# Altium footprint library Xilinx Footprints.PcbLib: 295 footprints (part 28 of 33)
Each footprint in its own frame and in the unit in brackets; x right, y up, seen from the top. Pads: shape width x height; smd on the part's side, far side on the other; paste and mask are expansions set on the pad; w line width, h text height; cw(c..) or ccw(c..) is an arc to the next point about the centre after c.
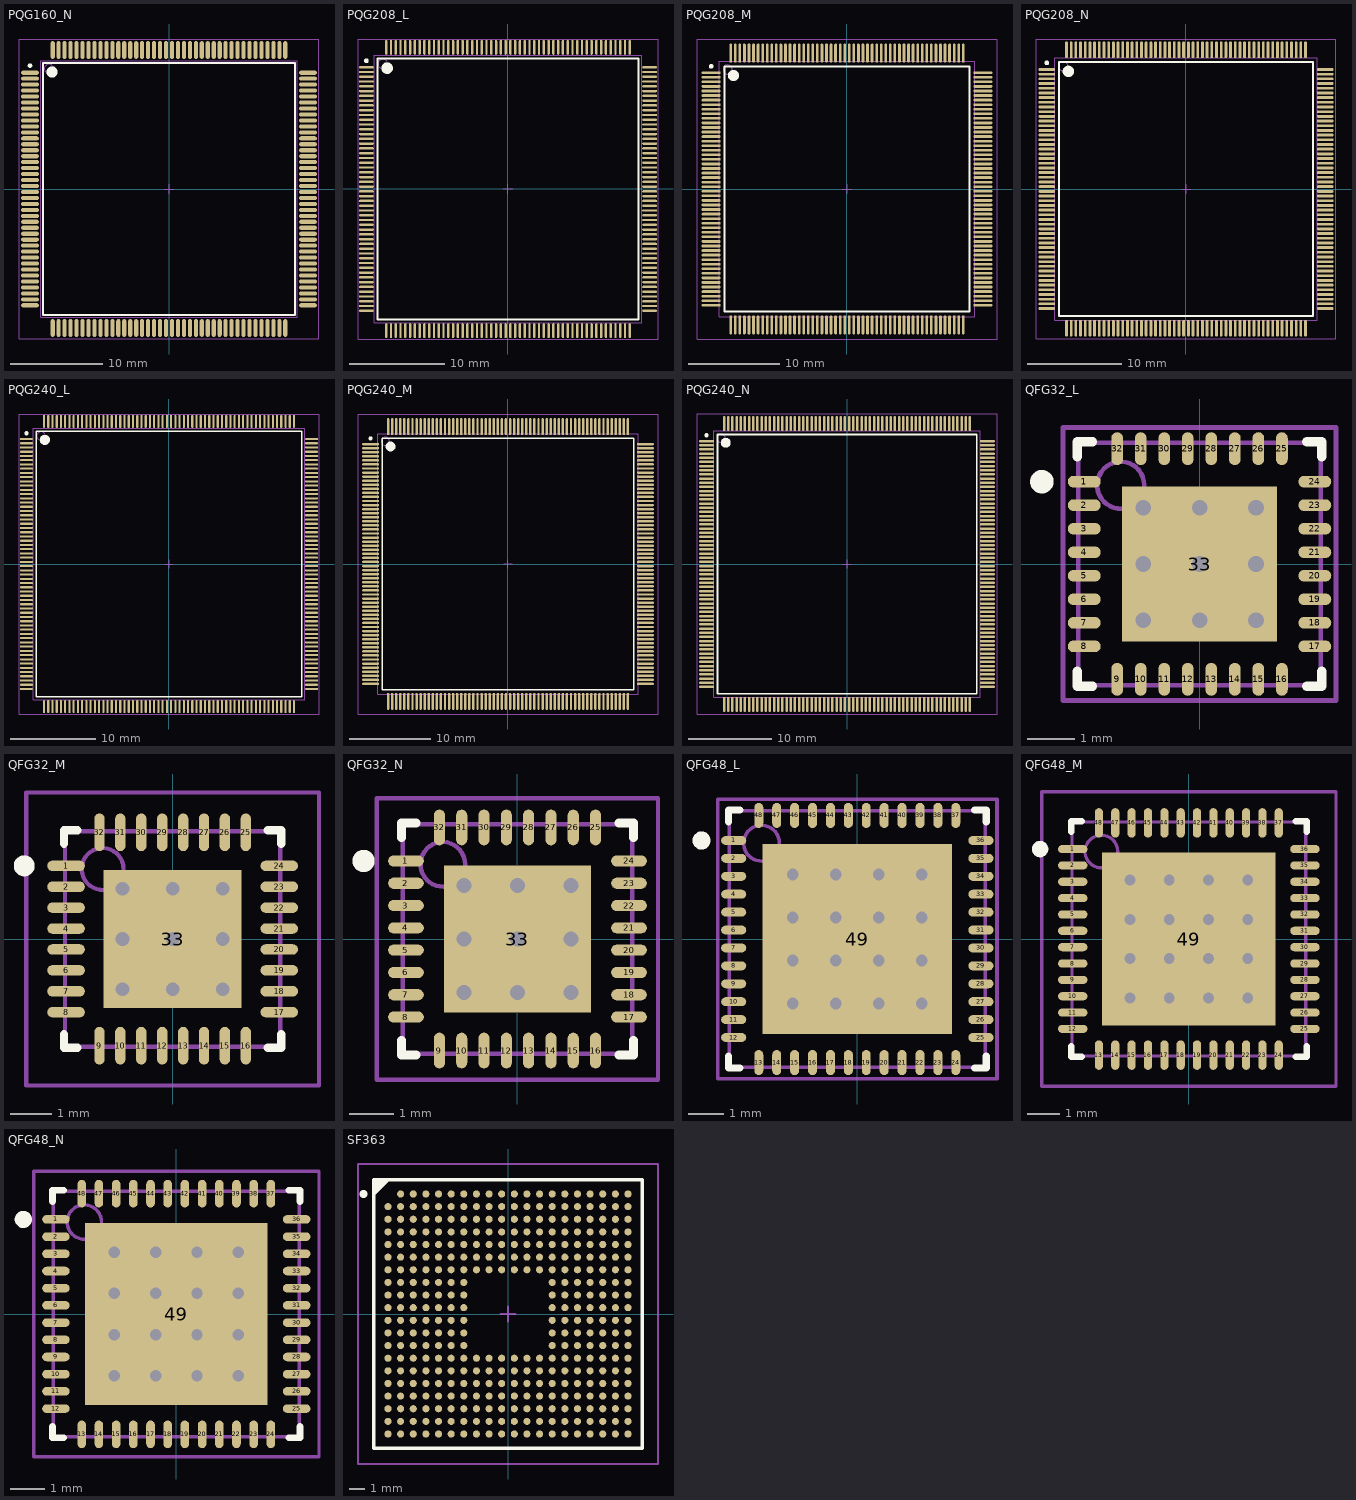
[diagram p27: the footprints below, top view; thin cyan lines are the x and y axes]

## PQG160_N [mm] "160-Pin Plastic Quad Flat Pack (PQG160) - Pb-Free, IPC Medium Density"
height 4.1
pads (160):
  oval 1.95x0.45 smd: 1(-15.15,12.675) 2(-15.15,12.025) 3(-15.15,11.375) 4(-15.15,10.725) 5(-15.15,10.075) 6(-15.15,9.425) 7(-15.15,8.775) 8(-15.15,8.125) 9(-15.15,7.475) 10(-15.15,6.825) 11(-15.15,6.175) 12(-15.15,5.525) 13(-15.15,4.875) 14(-15.15,4.225) 15(-15.15,3.575) 16(-15.15,2.925) 17(-15.15,2.275) 18(-15.15,1.625) 19(-15.15,0.975) 20(-15.15,0.325) 21(-15.15,-0.325) 22(-15.15,-0.975) 23(-15.15,-1.625) 24(-15.15,-2.275) 25(-15.15,-2.925) 26(-15.15,-3.575) 27(-15.15,-4.225) 28(-15.15,-4.875) 29(-15.15,-5.525) 30(-15.15,-6.175) 31(-15.15,-6.825) 32(-15.15,-7.475) 33(-15.15,-8.125) 34(-15.15,-8.775) 35(-15.15,-9.425) 36(-15.15,-10.075) 37(-15.15,-10.725) 38(-15.15,-11.375) 39(-15.15,-12.025) 40(-15.15,-12.675) 81(15.15,-12.675) 82(15.15,-12.025) 83(15.15,-11.375) 84(15.15,-10.725) 85(15.15,-10.075) 86(15.15,-9.425) 87(15.15,-8.775) 88(15.15,-8.125) 89(15.15,-7.475) 90(15.15,-6.825) 91(15.15,-6.175) 92(15.15,-5.525) 93(15.15,-4.875) 94(15.15,-4.225) 95(15.15,-3.575) 96(15.15,-2.925) 97(15.15,-2.275) 98(15.15,-1.625) 99(15.15,-0.975) 100(15.15,-0.325) 101(15.15,0.325) 102(15.15,0.975) 103(15.15,1.625) 104(15.15,2.275) 105(15.15,2.925) 106(15.15,3.575) 107(15.15,4.225) 108(15.15,4.875) 109(15.15,5.525) 110(15.15,6.175) 111(15.15,6.825) 112(15.15,7.475) 113(15.15,8.125) 114(15.15,8.775) 115(15.15,9.425) 116(15.15,10.075) 117(15.15,10.725) 118(15.15,11.375) 119(15.15,12.025) 120(15.15,12.675)
  oval 0.45x1.95 smd: 41(-12.675,-15.15) 42(-12.025,-15.15) 43(-11.375,-15.15) 44(-10.725,-15.15) 45(-10.075,-15.15) 46(-9.425,-15.15) 47(-8.775,-15.15) 48(-8.125,-15.15) 49(-7.475,-15.15) 50(-6.825,-15.15) 51(-6.175,-15.15) 52(-5.525,-15.15) 53(-4.875,-15.15) 54(-4.225,-15.15) 55(-3.575,-15.15) 56(-2.925,-15.15) 57(-2.275,-15.15) 58(-1.625,-15.15) 59(-0.975,-15.15) 60(-0.325,-15.15) 61(0.325,-15.15) 62(0.975,-15.15) 63(1.625,-15.15) 64(2.275,-15.15) 65(2.925,-15.15) 66(3.575,-15.15) 67(4.225,-15.15) 68(4.875,-15.15) 69(5.525,-15.15) 70(6.175,-15.15) 71(6.825,-15.15) 72(7.475,-15.15) 73(8.125,-15.15) 74(8.775,-15.15) 75(9.425,-15.15) 76(10.075,-15.15) 77(10.725,-15.15) 78(11.375,-15.15) 79(12.025,-15.15) 80(12.675,-15.15) 121(12.675,15.15) 122(12.025,15.15) 123(11.375,15.15) 124(10.725,15.15) 125(10.075,15.15) 126(9.425,15.15) 127(8.775,15.15) 128(8.125,15.15) 129(7.475,15.15) 130(6.825,15.15) 131(6.175,15.15) 132(5.525,15.15) 133(4.875,15.15) 134(4.225,15.15) 135(3.575,15.15) 136(2.925,15.15) 137(2.275,15.15) 138(1.625,15.15) 139(0.975,15.15) 140(0.325,15.15) 141(-0.325,15.15) 142(-0.975,15.15) 143(-1.625,15.15) 144(-2.275,15.15) 145(-2.925,15.15) 146(-3.575,15.15) 147(-4.225,15.15) 148(-4.875,15.15) 149(-5.525,15.15) 150(-6.175,15.15) 151(-6.825,15.15) 152(-7.475,15.15) 153(-8.125,15.15) 154(-8.775,15.15) 155(-9.425,15.15) 156(-10.075,15.15) 157(-10.725,15.15) 158(-11.375,15.15) 159(-12.025,15.15) 160(-12.675,15.15)
Top Overlay:
  circle w0.6: c-12.75,12.75 r0.3
  circle w0.25: c-15.15,13.45 r0.125
  lines w0.2: -13.75,-13.75 13.75,-13.75 13.75,13.75 -13.75,13.75 -13.75,-13.75
Mechanical 13:
  circle w0.1: c-13.1,13.1 r0.5
  lines w0.1: -14,-14 14,-14 14,14 -14,14 -14,-14
Mechanical 15:
  lines w0.1: -0.5,0 0.5,0 ; 0,-0.5 0,0.5 ; -16.35,-16.35 16.35,-16.35 16.35,16.35 -16.35,16.35 -16.35,-16.35
3D body: height 4.1, standoff 0, extent -14,-14 14,14

## PQG208_L [mm] "208-Pin Plastic Quad Flat Pack (PQG208) - Pb-Free, IPC High Density"
height 4.1
pads (208):
  oval 1.55x0.25 smd: 1(-14.825,12.75) 2(-14.825,12.25) 3(-14.825,11.75) 4(-14.825,11.25) 5(-14.825,10.75) 6(-14.825,10.25) 7(-14.825,9.75) 8(-14.825,9.25) 9(-14.825,8.75) 10(-14.825,8.25) 11(-14.825,7.75) 12(-14.825,7.25) 13(-14.825,6.75) 14(-14.825,6.25) 15(-14.825,5.75) 16(-14.825,5.25) 17(-14.825,4.75) 18(-14.825,4.25) 19(-14.825,3.75) 20(-14.825,3.25) 21(-14.825,2.75) 22(-14.825,2.25) 23(-14.825,1.75) 24(-14.825,1.25) 25(-14.825,0.75) 26(-14.825,0.25) 27(-14.825,-0.25) 28(-14.825,-0.75) 29(-14.825,-1.25) 30(-14.825,-1.75) 31(-14.825,-2.25) 32(-14.825,-2.75) 33(-14.825,-3.25) 34(-14.825,-3.75) 35(-14.825,-4.25) 36(-14.825,-4.75) 37(-14.825,-5.25) 38(-14.825,-5.75) 39(-14.825,-6.25) 40(-14.825,-6.75) 41(-14.825,-7.25) 42(-14.825,-7.75) 43(-14.825,-8.25) 44(-14.825,-8.75) 45(-14.825,-9.25) 46(-14.825,-9.75) 47(-14.825,-10.25) 48(-14.825,-10.75) 49(-14.825,-11.25) 50(-14.825,-11.75) 51(-14.825,-12.25) 52(-14.825,-12.75) 105(14.825,-12.75) 106(14.825,-12.25) 107(14.825,-11.75) 108(14.825,-11.25) 109(14.825,-10.75) 110(14.825,-10.25) 111(14.825,-9.75) 112(14.825,-9.25) 113(14.825,-8.75) 114(14.825,-8.25) 115(14.825,-7.75) 116(14.825,-7.25) 117(14.825,-6.75) 118(14.825,-6.25) 119(14.825,-5.75) 120(14.825,-5.25) 121(14.825,-4.75) 122(14.825,-4.25) 123(14.825,-3.75) 124(14.825,-3.25) 125(14.825,-2.75) 126(14.825,-2.25) 127(14.825,-1.75) 128(14.825,-1.25) 129(14.825,-0.75) 130(14.825,-0.25) 131(14.825,0.25) 132(14.825,0.75) 133(14.825,1.25) 134(14.825,1.75) 135(14.825,2.25) 136(14.825,2.75) 137(14.825,3.25) 138(14.825,3.75) 139(14.825,4.25) 140(14.825,4.75) 141(14.825,5.25) 142(14.825,5.75) 143(14.825,6.25) 144(14.825,6.75) 145(14.825,7.25) 146(14.825,7.75) 147(14.825,8.25) 148(14.825,8.75) 149(14.825,9.25) 150(14.825,9.75) 151(14.825,10.25) 152(14.825,10.75) 153(14.825,11.25) 154(14.825,11.75) 155(14.825,12.25) 156(14.825,12.75)
  oval 0.25x1.55 smd: 53(-12.75,-14.825) 54(-12.25,-14.825) 55(-11.75,-14.825) 56(-11.25,-14.825) 57(-10.75,-14.825) 58(-10.25,-14.825) 59(-9.75,-14.825) 60(-9.25,-14.825) 61(-8.75,-14.825) 62(-8.25,-14.825) 63(-7.75,-14.825) 64(-7.25,-14.825) 65(-6.75,-14.825) 66(-6.25,-14.825) 67(-5.75,-14.825) 68(-5.25,-14.825) 69(-4.75,-14.825) 70(-4.25,-14.825) 71(-3.75,-14.825) 72(-3.25,-14.825) 73(-2.75,-14.825) 74(-2.25,-14.825) 75(-1.75,-14.825) 76(-1.25,-14.825) 77(-0.75,-14.825) 78(-0.25,-14.825) 79(0.25,-14.825) 80(0.75,-14.825) 81(1.25,-14.825) 82(1.75,-14.825) 83(2.25,-14.825) 84(2.75,-14.825) 85(3.25,-14.825) 86(3.75,-14.825) 87(4.25,-14.825) 88(4.75,-14.825) 89(5.25,-14.825) 90(5.75,-14.825) 91(6.25,-14.825) 92(6.75,-14.825) 93(7.25,-14.825) 94(7.75,-14.825) 95(8.25,-14.825) 96(8.75,-14.825) 97(9.25,-14.825) 98(9.75,-14.825) 99(10.25,-14.825) 100(10.75,-14.825) 101(11.25,-14.825) 102(11.75,-14.825) 103(12.25,-14.825) 104(12.75,-14.825) 157(12.75,14.825) 158(12.25,14.825) 159(11.75,14.825) 160(11.25,14.825) 161(10.75,14.825) 162(10.25,14.825) 163(9.75,14.825) 164(9.25,14.825) 165(8.75,14.825) 166(8.25,14.825) 167(7.75,14.825) 168(7.25,14.825) 169(6.75,14.825) 170(6.25,14.825) 171(5.75,14.825) 172(5.25,14.825) 173(4.75,14.825) 174(4.25,14.825) 175(3.75,14.825) 176(3.25,14.825) 177(2.75,14.825) 178(2.25,14.825) 179(1.75,14.825) 180(1.25,14.825) 181(0.75,14.825) 182(0.25,14.825) 183(-0.25,14.825) 184(-0.75,14.825) 185(-1.25,14.825) 186(-1.75,14.825) 187(-2.25,14.825) 188(-2.75,14.825) 189(-3.25,14.825) 190(-3.75,14.825) 191(-4.25,14.825) 192(-4.75,14.825) 193(-5.25,14.825) 194(-5.75,14.825) 195(-6.25,14.825) 196(-6.75,14.825) 197(-7.25,14.825) 198(-7.75,14.825) 199(-8.25,14.825) 200(-8.75,14.825) 201(-9.25,14.825) 202(-9.75,14.825) 203(-10.25,14.825) 204(-10.75,14.825) 205(-11.25,14.825) 206(-11.75,14.825) 207(-12.25,14.825) 208(-12.75,14.825)
Top Overlay:
  circle w0.6: c-12.65,12.65 r0.3
  circle w0.25: c-14.825,13.425 r0.125
  lines w0.2: -13.65,-13.65 13.65,-13.65 13.65,13.65 -13.65,13.65 -13.65,-13.65
Mechanical 13:
  circle w0.1: c-13.1,13.1 r0.5
  lines w0.1: -14,-14 14,-14 14,14 -14,14 -14,-14
Mechanical 15:
  lines w0.1: -0.5,0 0.5,0 ; 0,-0.5 0,0.5 ; -15.7,-15.7 15.7,-15.7 15.7,15.7 -15.7,15.7 -15.7,-15.7
3D body: height 4.1, standoff 0, extent -14,-14 14,14

## PQG208_M [mm] "208-Pin Plastic Quad Flat Pack (PQG208) - Pb-Free, IPC Low Density"
height 4.1
pads (208):
  oval 2.1x0.3 smd: 1(-14.9,12.75) 2(-14.9,12.25) 3(-14.9,11.75) 4(-14.9,11.25) 5(-14.9,10.75) 6(-14.9,10.25) 7(-14.9,9.75) 8(-14.9,9.25) 9(-14.9,8.75) 10(-14.9,8.25) 11(-14.9,7.75) 12(-14.9,7.25) 13(-14.9,6.75) 14(-14.9,6.25) 15(-14.9,5.75) 16(-14.9,5.25) 17(-14.9,4.75) 18(-14.9,4.25) 19(-14.9,3.75) 20(-14.9,3.25) 21(-14.9,2.75) 22(-14.9,2.25) 23(-14.9,1.75) 24(-14.9,1.25) 25(-14.9,0.75) 26(-14.9,0.25) 27(-14.9,-0.25) 28(-14.9,-0.75) 29(-14.9,-1.25) 30(-14.9,-1.75) 31(-14.9,-2.25) 32(-14.9,-2.75) 33(-14.9,-3.25) 34(-14.9,-3.75) 35(-14.9,-4.25) 36(-14.9,-4.75) 37(-14.9,-5.25) 38(-14.9,-5.75) 39(-14.9,-6.25) 40(-14.9,-6.75) 41(-14.9,-7.25) 42(-14.9,-7.75) 43(-14.9,-8.25) 44(-14.9,-8.75) 45(-14.9,-9.25) 46(-14.9,-9.75) 47(-14.9,-10.25) 48(-14.9,-10.75) 49(-14.9,-11.25) 50(-14.9,-11.75) 51(-14.9,-12.25) 52(-14.9,-12.75) 105(14.9,-12.75) 106(14.9,-12.25) 107(14.9,-11.75) 108(14.9,-11.25) 109(14.9,-10.75) 110(14.9,-10.25) 111(14.9,-9.75) 112(14.9,-9.25) 113(14.9,-8.75) 114(14.9,-8.25) 115(14.9,-7.75) 116(14.9,-7.25) 117(14.9,-6.75) 118(14.9,-6.25) 119(14.9,-5.75) 120(14.9,-5.25) 121(14.9,-4.75) 122(14.9,-4.25) 123(14.9,-3.75) 124(14.9,-3.25) 125(14.9,-2.75) 126(14.9,-2.25) 127(14.9,-1.75) 128(14.9,-1.25) 129(14.9,-0.75) 130(14.9,-0.25) 131(14.9,0.25) 132(14.9,0.75) 133(14.9,1.25) 134(14.9,1.75) 135(14.9,2.25) 136(14.9,2.75) 137(14.9,3.25) 138(14.9,3.75) 139(14.9,4.25) 140(14.9,4.75) 141(14.9,5.25) 142(14.9,5.75) 143(14.9,6.25) 144(14.9,6.75) 145(14.9,7.25) 146(14.9,7.75) 147(14.9,8.25) 148(14.9,8.75) 149(14.9,9.25) 150(14.9,9.75) 151(14.9,10.25) 152(14.9,10.75) 153(14.9,11.25) 154(14.9,11.75) 155(14.9,12.25) 156(14.9,12.75)
  oval 0.3x2.1 smd: 53(-12.75,-14.9) 54(-12.25,-14.9) 55(-11.75,-14.9) 56(-11.25,-14.9) 57(-10.75,-14.9) 58(-10.25,-14.9) 59(-9.75,-14.9) 60(-9.25,-14.9) 61(-8.75,-14.9) 62(-8.25,-14.9) 63(-7.75,-14.9) 64(-7.25,-14.9) 65(-6.75,-14.9) 66(-6.25,-14.9) 67(-5.75,-14.9) 68(-5.25,-14.9) 69(-4.75,-14.9) 70(-4.25,-14.9) 71(-3.75,-14.9) 72(-3.25,-14.9) 73(-2.75,-14.9) 74(-2.25,-14.9) 75(-1.75,-14.9) 76(-1.25,-14.9) 77(-0.75,-14.9) 78(-0.25,-14.9) 79(0.25,-14.9) 80(0.75,-14.9) 81(1.25,-14.9) 82(1.75,-14.9) 83(2.25,-14.9) 84(2.75,-14.9) 85(3.25,-14.9) 86(3.75,-14.9) 87(4.25,-14.9) 88(4.75,-14.9) 89(5.25,-14.9) 90(5.75,-14.9) 91(6.25,-14.9) 92(6.75,-14.9) 93(7.25,-14.9) 94(7.75,-14.9) 95(8.25,-14.9) 96(8.75,-14.9) 97(9.25,-14.9) 98(9.75,-14.9) 99(10.25,-14.9) 100(10.75,-14.9) 101(11.25,-14.9) 102(11.75,-14.9) 103(12.25,-14.9) 104(12.75,-14.9) 157(12.75,14.9) 158(12.25,14.9) 159(11.75,14.9) 160(11.25,14.9) 161(10.75,14.9) 162(10.25,14.9) 163(9.75,14.9) 164(9.25,14.9) 165(8.75,14.9) 166(8.25,14.9) 167(7.75,14.9) 168(7.25,14.9) 169(6.75,14.9) 170(6.25,14.9) 171(5.75,14.9) 172(5.25,14.9) 173(4.75,14.9) 174(4.25,14.9) 175(3.75,14.9) 176(3.25,14.9) 177(2.75,14.9) 178(2.25,14.9) 179(1.75,14.9) 180(1.25,14.9) 181(0.75,14.9) 182(0.25,14.9) 183(-0.25,14.9) 184(-0.75,14.9) 185(-1.25,14.9) 186(-1.75,14.9) 187(-2.25,14.9) 188(-2.75,14.9) 189(-3.25,14.9) 190(-3.75,14.9) 191(-4.25,14.9) 192(-4.75,14.9) 193(-5.25,14.9) 194(-5.75,14.9) 195(-6.25,14.9) 196(-6.75,14.9) 197(-7.25,14.9) 198(-7.75,14.9) 199(-8.25,14.9) 200(-8.75,14.9) 201(-9.25,14.9) 202(-9.75,14.9) 203(-10.25,14.9) 204(-10.75,14.9) 205(-11.25,14.9) 206(-11.75,14.9) 207(-12.25,14.9) 208(-12.75,14.9)
Top Overlay:
  circle w0.6: c-12.45,12.45 r0.3
  circle w0.25: c-14.9,13.45 r0.125
  lines w0.2: -13.45,-13.45 13.45,-13.45 13.45,13.45 -13.45,13.45 -13.45,-13.45
Mechanical 13:
  circle w0.1: c-13.1,13.1 r0.5
  lines w0.1: -14,-14 14,-14 14,14 -14,14 -14,-14
Mechanical 15:
  lines w0.1: -0.5,0 0.5,0 ; 0,-0.5 0,0.5 ; -16.45,-16.45 16.45,-16.45 16.45,16.45 -16.45,16.45 -16.45,-16.45
3D body: height 4.1, standoff 0, extent -14,-14 14,14

## PQG208_N [mm] "208-Pin Plastic Quad Flat Pack (PQG208) - Pb-Free, IPC Medium Density"
height 4.1
pads (208):
  oval 1.8x0.3 smd: 1(-14.85,12.75) 2(-14.85,12.25) 3(-14.85,11.75) 4(-14.85,11.25) 5(-14.85,10.75) 6(-14.85,10.25) 7(-14.85,9.75) 8(-14.85,9.25) 9(-14.85,8.75) 10(-14.85,8.25) 11(-14.85,7.75) 12(-14.85,7.25) 13(-14.85,6.75) 14(-14.85,6.25) 15(-14.85,5.75) 16(-14.85,5.25) 17(-14.85,4.75) 18(-14.85,4.25) 19(-14.85,3.75) 20(-14.85,3.25) 21(-14.85,2.75) 22(-14.85,2.25) 23(-14.85,1.75) 24(-14.85,1.25) 25(-14.85,0.75) 26(-14.85,0.25) 27(-14.85,-0.25) 28(-14.85,-0.75) 29(-14.85,-1.25) 30(-14.85,-1.75) 31(-14.85,-2.25) 32(-14.85,-2.75) 33(-14.85,-3.25) 34(-14.85,-3.75) 35(-14.85,-4.25) 36(-14.85,-4.75) 37(-14.85,-5.25) 38(-14.85,-5.75) 39(-14.85,-6.25) 40(-14.85,-6.75) 41(-14.85,-7.25) 42(-14.85,-7.75) 43(-14.85,-8.25) 44(-14.85,-8.75) 45(-14.85,-9.25) 46(-14.85,-9.75) 47(-14.85,-10.25) 48(-14.85,-10.75) 49(-14.85,-11.25) 50(-14.85,-11.75) 51(-14.85,-12.25) 52(-14.85,-12.75) 105(14.85,-12.75) 106(14.85,-12.25) 107(14.85,-11.75) 108(14.85,-11.25) 109(14.85,-10.75) 110(14.85,-10.25) 111(14.85,-9.75) 112(14.85,-9.25) 113(14.85,-8.75) 114(14.85,-8.25) 115(14.85,-7.75) 116(14.85,-7.25) 117(14.85,-6.75) 118(14.85,-6.25) 119(14.85,-5.75) 120(14.85,-5.25) 121(14.85,-4.75) 122(14.85,-4.25) 123(14.85,-3.75) 124(14.85,-3.25) 125(14.85,-2.75) 126(14.85,-2.25) 127(14.85,-1.75) 128(14.85,-1.25) 129(14.85,-0.75) 130(14.85,-0.25) 131(14.85,0.25) 132(14.85,0.75) 133(14.85,1.25) 134(14.85,1.75) 135(14.85,2.25) 136(14.85,2.75) 137(14.85,3.25) 138(14.85,3.75) 139(14.85,4.25) 140(14.85,4.75) 141(14.85,5.25) 142(14.85,5.75) 143(14.85,6.25) 144(14.85,6.75) 145(14.85,7.25) 146(14.85,7.75) 147(14.85,8.25) 148(14.85,8.75) 149(14.85,9.25) 150(14.85,9.75) 151(14.85,10.25) 152(14.85,10.75) 153(14.85,11.25) 154(14.85,11.75) 155(14.85,12.25) 156(14.85,12.75)
  oval 0.3x1.8 smd: 53(-12.75,-14.85) 54(-12.25,-14.85) 55(-11.75,-14.85) 56(-11.25,-14.85) 57(-10.75,-14.85) 58(-10.25,-14.85) 59(-9.75,-14.85) 60(-9.25,-14.85) 61(-8.75,-14.85) 62(-8.25,-14.85) 63(-7.75,-14.85) 64(-7.25,-14.85) 65(-6.75,-14.85) 66(-6.25,-14.85) 67(-5.75,-14.85) 68(-5.25,-14.85) 69(-4.75,-14.85) 70(-4.25,-14.85) 71(-3.75,-14.85) 72(-3.25,-14.85) 73(-2.75,-14.85) 74(-2.25,-14.85) 75(-1.75,-14.85) 76(-1.25,-14.85) 77(-0.75,-14.85) 78(-0.25,-14.85) 79(0.25,-14.85) 80(0.75,-14.85) 81(1.25,-14.85) 82(1.75,-14.85) 83(2.25,-14.85) 84(2.75,-14.85) 85(3.25,-14.85) 86(3.75,-14.85) 87(4.25,-14.85) 88(4.75,-14.85) 89(5.25,-14.85) 90(5.75,-14.85) 91(6.25,-14.85) 92(6.75,-14.85) 93(7.25,-14.85) 94(7.75,-14.85) 95(8.25,-14.85) 96(8.75,-14.85) 97(9.25,-14.85) 98(9.75,-14.85) 99(10.25,-14.85) 100(10.75,-14.85) 101(11.25,-14.85) 102(11.75,-14.85) 103(12.25,-14.85) 104(12.75,-14.85) 157(12.75,14.85) 158(12.25,14.85) 159(11.75,14.85) 160(11.25,14.85) 161(10.75,14.85) 162(10.25,14.85) 163(9.75,14.85) 164(9.25,14.85) 165(8.75,14.85) 166(8.25,14.85) 167(7.75,14.85) 168(7.25,14.85) 169(6.75,14.85) 170(6.25,14.85) 171(5.75,14.85) 172(5.25,14.85) 173(4.75,14.85) 174(4.25,14.85) 175(3.75,14.85) 176(3.25,14.85) 177(2.75,14.85) 178(2.25,14.85) 179(1.75,14.85) 180(1.25,14.85) 181(0.75,14.85) 182(0.25,14.85) 183(-0.25,14.85) 184(-0.75,14.85) 185(-1.25,14.85) 186(-1.75,14.85) 187(-2.25,14.85) 188(-2.75,14.85) 189(-3.25,14.85) 190(-3.75,14.85) 191(-4.25,14.85) 192(-4.75,14.85) 193(-5.25,14.85) 194(-5.75,14.85) 195(-6.25,14.85) 196(-6.75,14.85) 197(-7.25,14.85) 198(-7.75,14.85) 199(-8.25,14.85) 200(-8.75,14.85) 201(-9.25,14.85) 202(-9.75,14.85) 203(-10.25,14.85) 204(-10.75,14.85) 205(-11.25,14.85) 206(-11.75,14.85) 207(-12.25,14.85) 208(-12.75,14.85)
Top Overlay:
  circle w0.6: c-12.55,12.55 r0.3
  circle w0.25: c-14.85,13.45 r0.125
  lines w0.2: -13.55,-13.55 13.55,-13.55 13.55,13.55 -13.55,13.55 -13.55,-13.55
Mechanical 13:
  circle w0.1: c-13.1,13.1 r0.5
  lines w0.1: -14,-14 14,-14 14,14 -14,14 -14,-14
Mechanical 15:
  lines w0.1: -0.5,0 0.5,0 ; 0,-0.5 0,0.5 ; -16,-16 16,-16 16,16 -16,16 -16,-16
3D body: height 4.1, standoff 0, extent -14,-14 14,14

## PQG240_L [mm] "240-Pin Plastic Quad Flat Pack (PQG240) - Pb-Free, IPC High Density"
height 4.1
pads (240):
  oval 1.55x0.25 smd: 1(-16.825,14.75) 2(-16.825,14.25) 3(-16.825,13.75) 4(-16.825,13.25) 5(-16.825,12.75) 6(-16.825,12.25) 7(-16.825,11.75) 8(-16.825,11.25) 9(-16.825,10.75) 10(-16.825,10.25) 11(-16.825,9.75) 12(-16.825,9.25) 13(-16.825,8.75) 14(-16.825,8.25) 15(-16.825,7.75) 16(-16.825,7.25) 17(-16.825,6.75) 18(-16.825,6.25) 19(-16.825,5.75) 20(-16.825,5.25) 21(-16.825,4.75) 22(-16.825,4.25) 23(-16.825,3.75) 24(-16.825,3.25) 25(-16.825,2.75) 26(-16.825,2.25) 27(-16.825,1.75) 28(-16.825,1.25) 29(-16.825,0.75) 30(-16.825,0.25) 31(-16.825,-0.25) 32(-16.825,-0.75) 33(-16.825,-1.25) 34(-16.825,-1.75) 35(-16.825,-2.25) 36(-16.825,-2.75) 37(-16.825,-3.25) 38(-16.825,-3.75) 39(-16.825,-4.25) 40(-16.825,-4.75) 41(-16.825,-5.25) 42(-16.825,-5.75) 43(-16.825,-6.25) 44(-16.825,-6.75) 45(-16.825,-7.25) 46(-16.825,-7.75) 47(-16.825,-8.25) 48(-16.825,-8.75) 49(-16.825,-9.25) 50(-16.825,-9.75) 51(-16.825,-10.25) 52(-16.825,-10.75) 53(-16.825,-11.25) 54(-16.825,-11.75) 55(-16.825,-12.25) 56(-16.825,-12.75) 57(-16.825,-13.25) 58(-16.825,-13.75) 59(-16.825,-14.25) 60(-16.825,-14.75) 121(16.825,-14.75) 122(16.825,-14.25) 123(16.825,-13.75) 124(16.825,-13.25) 125(16.825,-12.75) 126(16.825,-12.25) 127(16.825,-11.75) 128(16.825,-11.25) 129(16.825,-10.75) 130(16.825,-10.25) 131(16.825,-9.75) 132(16.825,-9.25) 133(16.825,-8.75) 134(16.825,-8.25) 135(16.825,-7.75) 136(16.825,-7.25) 137(16.825,-6.75) 138(16.825,-6.25) 139(16.825,-5.75) 140(16.825,-5.25) 141(16.825,-4.75) 142(16.825,-4.25) 143(16.825,-3.75) 144(16.825,-3.25) 145(16.825,-2.75) 146(16.825,-2.25) 147(16.825,-1.75) 148(16.825,-1.25) 149(16.825,-0.75) 150(16.825,-0.25) 151(16.825,0.25) 152(16.825,0.75) 153(16.825,1.25) 154(16.825,1.75) 155(16.825,2.25) 156(16.825,2.75) 157(16.825,3.25) 158(16.825,3.75) 159(16.825,4.25) 160(16.825,4.75) 161(16.825,5.25) 162(16.825,5.75) 163(16.825,6.25) 164(16.825,6.75) 165(16.825,7.25) 166(16.825,7.75) 167(16.825,8.25) 168(16.825,8.75) 169(16.825,9.25) 170(16.825,9.75) 171(16.825,10.25) 172(16.825,10.75) 173(16.825,11.25) 174(16.825,11.75) 175(16.825,12.25) 176(16.825,12.75) 177(16.825,13.25) 178(16.825,13.75) 179(16.825,14.25) 180(16.825,14.75)
  oval 0.25x1.55 smd: 61(-14.75,-16.825) 62(-14.25,-16.825) 63(-13.75,-16.825) 64(-13.25,-16.825) 65(-12.75,-16.825) 66(-12.25,-16.825) 67(-11.75,-16.825) 68(-11.25,-16.825) 69(-10.75,-16.825) 70(-10.25,-16.825) 71(-9.75,-16.825) 72(-9.25,-16.825) 73(-8.75,-16.825) 74(-8.25,-16.825) 75(-7.75,-16.825) 76(-7.25,-16.825) 77(-6.75,-16.825) 78(-6.25,-16.825) 79(-5.75,-16.825) 80(-5.25,-16.825) 81(-4.75,-16.825) 82(-4.25,-16.825) 83(-3.75,-16.825) 84(-3.25,-16.825) 85(-2.75,-16.825) 86(-2.25,-16.825) 87(-1.75,-16.825) 88(-1.25,-16.825) 89(-0.75,-16.825) 90(-0.25,-16.825) 91(0.25,-16.825) 92(0.75,-16.825) 93(1.25,-16.825) 94(1.75,-16.825) 95(2.25,-16.825) 96(2.75,-16.825) 97(3.25,-16.825) 98(3.75,-16.825) 99(4.25,-16.825) 100(4.75,-16.825) 101(5.25,-16.825) 102(5.75,-16.825) 103(6.25,-16.825) 104(6.75,-16.825) 105(7.25,-16.825) 106(7.75,-16.825) 107(8.25,-16.825) 108(8.75,-16.825) 109(9.25,-16.825) 110(9.75,-16.825) 111(10.25,-16.825) 112(10.75,-16.825) 113(11.25,-16.825) 114(11.75,-16.825) 115(12.25,-16.825) 116(12.75,-16.825) 117(13.25,-16.825) 118(13.75,-16.825) 119(14.25,-16.825) 120(14.75,-16.825) 181(14.75,16.825) 182(14.25,16.825) 183(13.75,16.825) 184(13.25,16.825) 185(12.75,16.825) 186(12.25,16.825) 187(11.75,16.825) 188(11.25,16.825) 189(10.75,16.825) 190(10.25,16.825) 191(9.75,16.825) 192(9.25,16.825) 193(8.75,16.825) 194(8.25,16.825) 195(7.75,16.825) 196(7.25,16.825) 197(6.75,16.825) 198(6.25,16.825) 199(5.75,16.825) 200(5.25,16.825) 201(4.75,16.825) 202(4.25,16.825) 203(3.75,16.825) 204(3.25,16.825) 205(2.75,16.825) 206(2.25,16.825) 207(1.75,16.825) 208(1.25,16.825) 209(0.75,16.825) 210(0.25,16.825) 211(-0.25,16.825) 212(-0.75,16.825) 213(-1.25,16.825) 214(-1.75,16.825) 215(-2.25,16.825) 216(-2.75,16.825) 217(-3.25,16.825) 218(-3.75,16.825) 219(-4.25,16.825) 220(-4.75,16.825) 221(-5.25,16.825) 222(-5.75,16.825) 223(-6.25,16.825) 224(-6.75,16.825) 225(-7.25,16.825) 226(-7.75,16.825) 227(-8.25,16.825) 228(-8.75,16.825) 229(-9.25,16.825) 230(-9.75,16.825) 231(-10.25,16.825) 232(-10.75,16.825) 233(-11.25,16.825) 234(-11.75,16.825) 235(-12.25,16.825) 236(-12.75,16.825) 237(-13.25,16.825) 238(-13.75,16.825) 239(-14.25,16.825) 240(-14.75,16.825)
Top Overlay:
  circle w0.6: c-14.65,14.65 r0.3
  circle w0.25: c-16.825,15.425 r0.125
  lines w0.2: -15.65,-15.65 15.65,-15.65 15.65,15.65 -15.65,15.65 -15.65,-15.65
Mechanical 13:
  circle w0.1: c-15.1,15.1 r0.5
  lines w0.1: -16,-16 16,-16 16,16 -16,16 -16,-16
Mechanical 15:
  lines w0.1: -0.5,0 0.5,0 ; 0,-0.5 0,0.5 ; -17.7,-17.7 17.7,-17.7 17.7,17.7 -17.7,17.7 -17.7,-17.7
3D body: height 4.1, standoff 0, extent -16,-16 16,16

## PQG240_M [mm] "240-Pin Plastic Quad Flat Pack (PQG240) - Pb-Free, IPC Low Density"
height 4.1
pads (240):
  oval 2.1x0.3 smd: 1(-16.9,14.75) 2(-16.9,14.25) 3(-16.9,13.75) 4(-16.9,13.25) 5(-16.9,12.75) 6(-16.9,12.25) 7(-16.9,11.75) 8(-16.9,11.25) 9(-16.9,10.75) 10(-16.9,10.25) 11(-16.9,9.75) 12(-16.9,9.25) 13(-16.9,8.75) 14(-16.9,8.25) 15(-16.9,7.75) 16(-16.9,7.25) 17(-16.9,6.75) 18(-16.9,6.25) 19(-16.9,5.75) 20(-16.9,5.25) 21(-16.9,4.75) 22(-16.9,4.25) 23(-16.9,3.75) 24(-16.9,3.25) 25(-16.9,2.75) 26(-16.9,2.25) 27(-16.9,1.75) 28(-16.9,1.25) 29(-16.9,0.75) 30(-16.9,0.25) 31(-16.9,-0.25) 32(-16.9,-0.75) 33(-16.9,-1.25) 34(-16.9,-1.75) 35(-16.9,-2.25) 36(-16.9,-2.75) 37(-16.9,-3.25) 38(-16.9,-3.75) 39(-16.9,-4.25) 40(-16.9,-4.75) 41(-16.9,-5.25) 42(-16.9,-5.75) 43(-16.9,-6.25) 44(-16.9,-6.75) 45(-16.9,-7.25) 46(-16.9,-7.75) 47(-16.9,-8.25) 48(-16.9,-8.75) 49(-16.9,-9.25) 50(-16.9,-9.75) 51(-16.9,-10.25) 52(-16.9,-10.75) 53(-16.9,-11.25) 54(-16.9,-11.75) 55(-16.9,-12.25) 56(-16.9,-12.75) 57(-16.9,-13.25) 58(-16.9,-13.75) 59(-16.9,-14.25) 60(-16.9,-14.75) 121(16.9,-14.75) 122(16.9,-14.25) 123(16.9,-13.75) 124(16.9,-13.25) 125(16.9,-12.75) 126(16.9,-12.25) 127(16.9,-11.75) 128(16.9,-11.25) 129(16.9,-10.75) 130(16.9,-10.25) 131(16.9,-9.75) 132(16.9,-9.25) 133(16.9,-8.75) 134(16.9,-8.25) 135(16.9,-7.75) 136(16.9,-7.25) 137(16.9,-6.75) 138(16.9,-6.25) 139(16.9,-5.75) 140(16.9,-5.25) 141(16.9,-4.75) 142(16.9,-4.25) 143(16.9,-3.75) 144(16.9,-3.25) 145(16.9,-2.75) 146(16.9,-2.25) 147(16.9,-1.75) 148(16.9,-1.25) 149(16.9,-0.75) 150(16.9,-0.25) 151(16.9,0.25) 152(16.9,0.75) 153(16.9,1.25) 154(16.9,1.75) 155(16.9,2.25) 156(16.9,2.75) 157(16.9,3.25) 158(16.9,3.75) 159(16.9,4.25) 160(16.9,4.75) 161(16.9,5.25) 162(16.9,5.75) 163(16.9,6.25) 164(16.9,6.75) 165(16.9,7.25) 166(16.9,7.75) 167(16.9,8.25) 168(16.9,8.75) 169(16.9,9.25) 170(16.9,9.75) 171(16.9,10.25) 172(16.9,10.75) 173(16.9,11.25) 174(16.9,11.75) 175(16.9,12.25) 176(16.9,12.75) 177(16.9,13.25) 178(16.9,13.75) 179(16.9,14.25) 180(16.9,14.75)
  oval 0.3x2.1 smd: 61(-14.75,-16.9) 62(-14.25,-16.9) 63(-13.75,-16.9) 64(-13.25,-16.9) 65(-12.75,-16.9) 66(-12.25,-16.9) 67(-11.75,-16.9) 68(-11.25,-16.9) 69(-10.75,-16.9) 70(-10.25,-16.9) 71(-9.75,-16.9) 72(-9.25,-16.9) 73(-8.75,-16.9) 74(-8.25,-16.9) 75(-7.75,-16.9) 76(-7.25,-16.9) 77(-6.75,-16.9) 78(-6.25,-16.9) 79(-5.75,-16.9) 80(-5.25,-16.9) 81(-4.75,-16.9) 82(-4.25,-16.9) 83(-3.75,-16.9) 84(-3.25,-16.9) 85(-2.75,-16.9) 86(-2.25,-16.9) 87(-1.75,-16.9) 88(-1.25,-16.9) 89(-0.75,-16.9) 90(-0.25,-16.9) 91(0.25,-16.9) 92(0.75,-16.9) 93(1.25,-16.9) 94(1.75,-16.9) 95(2.25,-16.9) 96(2.75,-16.9) 97(3.25,-16.9) 98(3.75,-16.9) 99(4.25,-16.9) 100(4.75,-16.9) 101(5.25,-16.9) 102(5.75,-16.9) 103(6.25,-16.9) 104(6.75,-16.9) 105(7.25,-16.9) 106(7.75,-16.9) 107(8.25,-16.9) 108(8.75,-16.9) 109(9.25,-16.9) 110(9.75,-16.9) 111(10.25,-16.9) 112(10.75,-16.9) 113(11.25,-16.9) 114(11.75,-16.9) 115(12.25,-16.9) 116(12.75,-16.9) 117(13.25,-16.9) 118(13.75,-16.9) 119(14.25,-16.9) 120(14.75,-16.9) 181(14.75,16.9) 182(14.25,16.9) 183(13.75,16.9) 184(13.25,16.9) 185(12.75,16.9) 186(12.25,16.9) 187(11.75,16.9) 188(11.25,16.9) 189(10.75,16.9) 190(10.25,16.9) 191(9.75,16.9) 192(9.25,16.9) 193(8.75,16.9) 194(8.25,16.9) 195(7.75,16.9) 196(7.25,16.9) 197(6.75,16.9) 198(6.25,16.9) 199(5.75,16.9) 200(5.25,16.9) 201(4.75,16.9) 202(4.25,16.9) 203(3.75,16.9) 204(3.25,16.9) 205(2.75,16.9) 206(2.25,16.9) 207(1.75,16.9) 208(1.25,16.9) 209(0.75,16.9) 210(0.25,16.9) 211(-0.25,16.9) 212(-0.75,16.9) 213(-1.25,16.9) 214(-1.75,16.9) 215(-2.25,16.9) 216(-2.75,16.9) 217(-3.25,16.9) 218(-3.75,16.9) 219(-4.25,16.9) 220(-4.75,16.9) 221(-5.25,16.9) 222(-5.75,16.9) 223(-6.25,16.9) 224(-6.75,16.9) 225(-7.25,16.9) 226(-7.75,16.9) 227(-8.25,16.9) 228(-8.75,16.9) 229(-9.25,16.9) 230(-9.75,16.9) 231(-10.25,16.9) 232(-10.75,16.9) 233(-11.25,16.9) 234(-11.75,16.9) 235(-12.25,16.9) 236(-12.75,16.9) 237(-13.25,16.9) 238(-13.75,16.9) 239(-14.25,16.9) 240(-14.75,16.9)
Top Overlay:
  circle w0.6: c-14.45,14.45 r0.3
  circle w0.25: c-16.9,15.45 r0.125
  lines w0.2: -15.45,-15.45 15.45,-15.45 15.45,15.45 -15.45,15.45 -15.45,-15.45
Mechanical 13:
  circle w0.1: c-15.1,15.1 r0.5
  lines w0.1: -16,-16 16,-16 16,16 -16,16 -16,-16
Mechanical 15:
  lines w0.1: -0.5,0 0.5,0 ; 0,-0.5 0,0.5 ; -18.45,-18.45 18.45,-18.45 18.45,18.45 -18.45,18.45 -18.45,-18.45
3D body: height 4.1, standoff 0, extent -16,-16 16,16

## PQG240_N [mm] "240-Pin Plastic Quad Flat Pack (PQG240) - Pb-Free, IPC Medium Density"
height 4.1
pads (240):
  oval 1.8x0.3 smd: 1(-16.85,14.75) 2(-16.85,14.25) 3(-16.85,13.75) 4(-16.85,13.25) 5(-16.85,12.75) 6(-16.85,12.25) 7(-16.85,11.75) 8(-16.85,11.25) 9(-16.85,10.75) 10(-16.85,10.25) 11(-16.85,9.75) 12(-16.85,9.25) 13(-16.85,8.75) 14(-16.85,8.25) 15(-16.85,7.75) 16(-16.85,7.25) 17(-16.85,6.75) 18(-16.85,6.25) 19(-16.85,5.75) 20(-16.85,5.25) 21(-16.85,4.75) 22(-16.85,4.25) 23(-16.85,3.75) 24(-16.85,3.25) 25(-16.85,2.75) 26(-16.85,2.25) 27(-16.85,1.75) 28(-16.85,1.25) 29(-16.85,0.75) 30(-16.85,0.25) 31(-16.85,-0.25) 32(-16.85,-0.75) 33(-16.85,-1.25) 34(-16.85,-1.75) 35(-16.85,-2.25) 36(-16.85,-2.75) 37(-16.85,-3.25) 38(-16.85,-3.75) 39(-16.85,-4.25) 40(-16.85,-4.75) 41(-16.85,-5.25) 42(-16.85,-5.75) 43(-16.85,-6.25) 44(-16.85,-6.75) 45(-16.85,-7.25) 46(-16.85,-7.75) 47(-16.85,-8.25) 48(-16.85,-8.75) 49(-16.85,-9.25) 50(-16.85,-9.75) 51(-16.85,-10.25) 52(-16.85,-10.75) 53(-16.85,-11.25) 54(-16.85,-11.75) 55(-16.85,-12.25) 56(-16.85,-12.75) 57(-16.85,-13.25) 58(-16.85,-13.75) 59(-16.85,-14.25) 60(-16.85,-14.75) 121(16.85,-14.75) 122(16.85,-14.25) 123(16.85,-13.75) 124(16.85,-13.25) 125(16.85,-12.75) 126(16.85,-12.25) 127(16.85,-11.75) 128(16.85,-11.25) 129(16.85,-10.75) 130(16.85,-10.25) 131(16.85,-9.75) 132(16.85,-9.25) 133(16.85,-8.75) 134(16.85,-8.25) 135(16.85,-7.75) 136(16.85,-7.25) 137(16.85,-6.75) 138(16.85,-6.25) 139(16.85,-5.75) 140(16.85,-5.25) 141(16.85,-4.75) 142(16.85,-4.25) 143(16.85,-3.75) 144(16.85,-3.25) 145(16.85,-2.75) 146(16.85,-2.25) 147(16.85,-1.75) 148(16.85,-1.25) 149(16.85,-0.75) 150(16.85,-0.25) 151(16.85,0.25) 152(16.85,0.75) 153(16.85,1.25) 154(16.85,1.75) 155(16.85,2.25) 156(16.85,2.75) 157(16.85,3.25) 158(16.85,3.75) 159(16.85,4.25) 160(16.85,4.75) 161(16.85,5.25) 162(16.85,5.75) 163(16.85,6.25) 164(16.85,6.75) 165(16.85,7.25) 166(16.85,7.75) 167(16.85,8.25) 168(16.85,8.75) 169(16.85,9.25) 170(16.85,9.75) 171(16.85,10.25) 172(16.85,10.75) 173(16.85,11.25) 174(16.85,11.75) 175(16.85,12.25) 176(16.85,12.75) 177(16.85,13.25) 178(16.85,13.75) 179(16.85,14.25) 180(16.85,14.75)
  oval 0.3x1.8 smd: 61(-14.75,-16.85) 62(-14.25,-16.85) 63(-13.75,-16.85) 64(-13.25,-16.85) 65(-12.75,-16.85) 66(-12.25,-16.85) 67(-11.75,-16.85) 68(-11.25,-16.85) 69(-10.75,-16.85) 70(-10.25,-16.85) 71(-9.75,-16.85) 72(-9.25,-16.85) 73(-8.75,-16.85) 74(-8.25,-16.85) 75(-7.75,-16.85) 76(-7.25,-16.85) 77(-6.75,-16.85) 78(-6.25,-16.85) 79(-5.75,-16.85) 80(-5.25,-16.85) 81(-4.75,-16.85) 82(-4.25,-16.85) 83(-3.75,-16.85) 84(-3.25,-16.85) 85(-2.75,-16.85) 86(-2.25,-16.85) 87(-1.75,-16.85) 88(-1.25,-16.85) 89(-0.75,-16.85) 90(-0.25,-16.85) 91(0.25,-16.85) 92(0.75,-16.85) 93(1.25,-16.85) 94(1.75,-16.85) 95(2.25,-16.85) 96(2.75,-16.85) 97(3.25,-16.85) 98(3.75,-16.85) 99(4.25,-16.85) 100(4.75,-16.85) 101(5.25,-16.85) 102(5.75,-16.85) 103(6.25,-16.85) 104(6.75,-16.85) 105(7.25,-16.85) 106(7.75,-16.85) 107(8.25,-16.85) 108(8.75,-16.85) 109(9.25,-16.85) 110(9.75,-16.85) 111(10.25,-16.85) 112(10.75,-16.85) 113(11.25,-16.85) 114(11.75,-16.85) 115(12.25,-16.85) 116(12.75,-16.85) 117(13.25,-16.85) 118(13.75,-16.85) 119(14.25,-16.85) 120(14.75,-16.85) 181(14.75,16.85) 182(14.25,16.85) 183(13.75,16.85) 184(13.25,16.85) 185(12.75,16.85) 186(12.25,16.85) 187(11.75,16.85) 188(11.25,16.85) 189(10.75,16.85) 190(10.25,16.85) 191(9.75,16.85) 192(9.25,16.85) 193(8.75,16.85) 194(8.25,16.85) 195(7.75,16.85) 196(7.25,16.85) 197(6.75,16.85) 198(6.25,16.85) 199(5.75,16.85) 200(5.25,16.85) 201(4.75,16.85) 202(4.25,16.85) 203(3.75,16.85) 204(3.25,16.85) 205(2.75,16.85) 206(2.25,16.85) 207(1.75,16.85) 208(1.25,16.85) 209(0.75,16.85) 210(0.25,16.85) 211(-0.25,16.85) 212(-0.75,16.85) 213(-1.25,16.85) 214(-1.75,16.85) 215(-2.25,16.85) 216(-2.75,16.85) 217(-3.25,16.85) 218(-3.75,16.85) 219(-4.25,16.85) 220(-4.75,16.85) 221(-5.25,16.85) 222(-5.75,16.85) 223(-6.25,16.85) 224(-6.75,16.85) 225(-7.25,16.85) 226(-7.75,16.85) 227(-8.25,16.85) 228(-8.75,16.85) 229(-9.25,16.85) 230(-9.75,16.85) 231(-10.25,16.85) 232(-10.75,16.85) 233(-11.25,16.85) 234(-11.75,16.85) 235(-12.25,16.85) 236(-12.75,16.85) 237(-13.25,16.85) 238(-13.75,16.85) 239(-14.25,16.85) 240(-14.75,16.85)
Top Overlay:
  circle w0.6: c-14.55,14.55 r0.3
  circle w0.25: c-16.85,15.45 r0.125
  lines w0.2: -15.55,-15.55 15.55,-15.55 15.55,15.55 -15.55,15.55 -15.55,-15.55
Mechanical 13:
  circle w0.1: c-15.1,15.1 r0.5
  lines w0.1: -16,-16 16,-16 16,16 -16,16 -16,-16
Mechanical 15:
  lines w0.1: -0.5,0 0.5,0 ; 0,-0.5 0,0.5 ; -18,-18 18,-18 18,18 -18,18 -18,-18
3D body: height 4.1, standoff 0, extent -16,-16 16,16

## QFG32_L [mm] "32-Pin Quad Flat No-Lead (QFG32) - Pb-Free, IPC High Density"
height 1
pads (33):
  oval 0.7x0.25 smd: 1(-2.45,1.75) 2(-2.45,1.25) 3(-2.45,0.75) 4(-2.45,0.25) 5(-2.45,-0.25) 6(-2.45,-0.75) 7(-2.45,-1.25) 8(-2.45,-1.75) 17(2.45,-1.75) 18(2.45,-1.25) 19(2.45,-0.75) 20(2.45,-0.25) 21(2.45,0.25) 22(2.45,0.75) 23(2.45,1.25) 24(2.45,1.75)
  oval 0.25x0.7 smd: 9(-1.75,-2.45) 10(-1.25,-2.45) 11(-0.75,-2.45) 12(-0.25,-2.45) 13(0.25,-2.45) 14(0.75,-2.45) 15(1.25,-2.45) 16(1.75,-2.45) 25(1.75,2.45) 26(1.25,2.45) 27(0.75,2.45) 28(0.25,2.45) 29(-0.25,2.45) 30(-0.75,2.45) 31(-1.25,2.45) 32(-1.75,2.45)
  rect 3.3x3.3 smd: 33(0,0)
via 1.2,-1.2 diameter 0.66 hole 0.33
via 0,-1.2 diameter 0.66 hole 0.33
via -1.2,-1.2 diameter 0.66 hole 0.33
via 1.2,0 diameter 0.66 hole 0.33
via 0,0 diameter 0.66 hole 0.33
via -1.2,0 diameter 0.66 hole 0.33
via 1.2,1.2 diameter 0.66 hole 0.33
via 0,1.2 diameter 0.66 hole 0.33
via -1.2,1.2 diameter 0.66 hole 0.33
Top Overlay:
  circle w0.25: c-3.35,1.75 r0.125
  lines w0.2: -2.6,-2.275 -2.6,-2.6 -2.275,-2.6 ; -2.6,2.275 -2.6,2.6 -2.275,2.6 ; 2.275,-2.6 2.6,-2.6 2.6,-2.275 ; 2.275,2.6 2.6,2.6 2.6,2.275
Mechanical 13:
  circle w0.1: c-1.675,1.675 r0.5
  lines w0.1: -2.575,-2.575 2.575,-2.575 2.575,2.575 -2.575,2.575 -2.575,-2.575
Mechanical 15:
  lines w0.1: -0.5,0 0.5,0 ; 0,-0.5 0,0.5 ; -2.9,-2.9 2.9,-2.9 2.9,2.9 -2.9,2.9 -2.9,-2.9
3D body: height 1, standoff 0, extent -2.575,-2.575 2.575,2.575

## QFG32_M [mm] "32-Pin Quad Flat No-Lead (QFG32) - Pb-Free, IPC Low Density"
height 1
pads (33):
  oval 0.9x0.25 smd: 1(-2.55,1.75) 2(-2.55,1.25) 3(-2.55,0.75) 4(-2.55,0.25) 5(-2.55,-0.25) 6(-2.55,-0.75) 7(-2.55,-1.25) 8(-2.55,-1.75) 17(2.55,-1.75) 18(2.55,-1.25) 19(2.55,-0.75) 20(2.55,-0.25) 21(2.55,0.25) 22(2.55,0.75) 23(2.55,1.25) 24(2.55,1.75)
  oval 0.25x0.9 smd: 9(-1.75,-2.55) 10(-1.25,-2.55) 11(-0.75,-2.55) 12(-0.25,-2.55) 13(0.25,-2.55) 14(0.75,-2.55) 15(1.25,-2.55) 16(1.75,-2.55) 25(1.75,2.55) 26(1.25,2.55) 27(0.75,2.55) 28(0.25,2.55) 29(-0.25,2.55) 30(-0.75,2.55) 31(-1.25,2.55) 32(-1.75,2.55)
  rect 3.3x3.3 smd: 33(0,0)
via 1.2,-1.2 diameter 0.66 hole 0.33
via 0,-1.2 diameter 0.66 hole 0.33
via -1.2,-1.2 diameter 0.66 hole 0.33
via 1.2,0 diameter 0.66 hole 0.33
via 0,0 diameter 0.66 hole 0.33
via -1.2,0 diameter 0.66 hole 0.33
via 1.2,1.2 diameter 0.66 hole 0.33
via 0,1.2 diameter 0.66 hole 0.33
via -1.2,1.2 diameter 0.66 hole 0.33
Top Overlay:
  circle w0.25: c-3.55,1.75 r0.125
  lines w0.2: -2.6,-2.275 -2.6,-2.6 -2.275,-2.6 ; -2.6,2.275 -2.6,2.6 -2.275,2.6 ; 2.275,-2.6 2.6,-2.6 2.6,-2.275 ; 2.275,2.6 2.6,2.6 2.6,2.275
Mechanical 13:
  circle w0.1: c-1.675,1.675 r0.5
  lines w0.1: -2.575,-2.575 2.575,-2.575 2.575,2.575 -2.575,2.575 -2.575,-2.575
Mechanical 15:
  lines w0.1: -0.5,0 0.5,0 ; 0,-0.5 0,0.5 ; -3.5,-3.5 3.5,-3.5 3.5,3.5 -3.5,3.5 -3.5,-3.5
3D body: height 1, standoff 0, extent -2.575,-2.575 2.575,2.575

## QFG32_N [mm] "32-Pin Quad Flat No-Lead (QFG32) - Pb-Free, IPC Medium Density"
height 1
pads (33):
  oval 0.8x0.25 smd: 1(-2.5,1.75) 2(-2.5,1.25) 3(-2.5,0.75) 4(-2.5,0.25) 5(-2.5,-0.25) 6(-2.5,-0.75) 7(-2.5,-1.25) 8(-2.5,-1.75) 17(2.5,-1.75) 18(2.5,-1.25) 19(2.5,-0.75) 20(2.5,-0.25) 21(2.5,0.25) 22(2.5,0.75) 23(2.5,1.25) 24(2.5,1.75)
  oval 0.25x0.8 smd: 9(-1.75,-2.5) 10(-1.25,-2.5) 11(-0.75,-2.5) 12(-0.25,-2.5) 13(0.25,-2.5) 14(0.75,-2.5) 15(1.25,-2.5) 16(1.75,-2.5) 25(1.75,2.5) 26(1.25,2.5) 27(0.75,2.5) 28(0.25,2.5) 29(-0.25,2.5) 30(-0.75,2.5) 31(-1.25,2.5) 32(-1.75,2.5)
  rect 3.3x3.3 smd: 33(0,0)
via 1.2,-1.2 diameter 0.66 hole 0.33
via 0,-1.2 diameter 0.66 hole 0.33
via -1.2,-1.2 diameter 0.66 hole 0.33
via 1.2,0 diameter 0.66 hole 0.33
via 0,0 diameter 0.66 hole 0.33
via -1.2,0 diameter 0.66 hole 0.33
via 1.2,1.2 diameter 0.66 hole 0.33
via 0,1.2 diameter 0.66 hole 0.33
via -1.2,1.2 diameter 0.66 hole 0.33
Top Overlay:
  circle w0.25: c-3.45,1.75 r0.125
  lines w0.2: -2.6,-2.275 -2.6,-2.6 -2.275,-2.6 ; -2.6,2.275 -2.6,2.6 -2.275,2.6 ; 2.275,-2.6 2.6,-2.6 2.6,-2.275 ; 2.275,2.6 2.6,2.6 2.6,2.275
Mechanical 13:
  circle w0.1: c-1.675,1.675 r0.5
  lines w0.1: -2.575,-2.575 2.575,-2.575 2.575,2.575 -2.575,2.575 -2.575,-2.575
Mechanical 15:
  lines w0.1: -0.5,0 0.5,0 ; 0,-0.5 0,0.5 ; -3.15,-3.15 3.15,-3.15 3.15,3.15 -3.15,3.15 -3.15,-3.15
3D body: height 1, standoff 0, extent -2.575,-2.575 2.575,2.575

## QFG48_L [mm] "48-Pin Quad Flat No-Lead (QFG48) - Pb-Free, IPC High Density"
height 1
pads (49):
  oval 0.7x0.25 smd: 1(-3.45,2.75) 2(-3.45,2.25) 3(-3.45,1.75) 4(-3.45,1.25) 5(-3.45,0.75) 6(-3.45,0.25) 7(-3.45,-0.25) 8(-3.45,-0.75) 9(-3.45,-1.25) 10(-3.45,-1.75) 11(-3.45,-2.25) 12(-3.45,-2.75) 25(3.45,-2.75) 26(3.45,-2.25) 27(3.45,-1.75) 28(3.45,-1.25) 29(3.45,-0.75) 30(3.45,-0.25) 31(3.45,0.25) 32(3.45,0.75) 33(3.45,1.25) 34(3.45,1.75) 35(3.45,2.25) 36(3.45,2.75)
  oval 0.25x0.7 smd: 13(-2.75,-3.45) 14(-2.25,-3.45) 15(-1.75,-3.45) 16(-1.25,-3.45) 17(-0.75,-3.45) 18(-0.25,-3.45) 19(0.25,-3.45) 20(0.75,-3.45) 21(1.25,-3.45) 22(1.75,-3.45) 23(2.25,-3.45) 24(2.75,-3.45) 37(2.75,3.45) 38(2.25,3.45) 39(1.75,3.45) 40(1.25,3.45) 41(0.75,3.45) 42(0.25,3.45) 43(-0.25,3.45) 44(-0.75,3.45) 45(-1.25,3.45) 46(-1.75,3.45) 47(-2.25,3.45) 48(-2.75,3.45)
  rect 5.3x5.3 smd: 49(0,0)
via 1.8,-1.8 diameter 0.66 hole 0.33
via 0.6,-1.8 diameter 0.66 hole 0.33
via -0.6,-1.8 diameter 0.66 hole 0.33
via -1.8,-1.8 diameter 0.66 hole 0.33
via 1.8,-0.6 diameter 0.66 hole 0.33
via 0.6,-0.6 diameter 0.66 hole 0.33
via -0.6,-0.6 diameter 0.66 hole 0.33
via -1.8,-0.6 diameter 0.66 hole 0.33
via 1.8,0.6 diameter 0.66 hole 0.33
via 0.6,0.6 diameter 0.66 hole 0.33
via -0.6,0.6 diameter 0.66 hole 0.33
via -1.8,0.6 diameter 0.66 hole 0.33
via 1.8,1.8 diameter 0.66 hole 0.33
via 0.6,1.8 diameter 0.66 hole 0.33
via -0.6,1.8 diameter 0.66 hole 0.33
via -1.8,1.8 diameter 0.66 hole 0.33
Top Overlay:
  circle w0.25: c-4.35,2.75 r0.125
  lines w0.2: -3.6,-3.275 -3.6,-3.6 -3.275,-3.6 ; -3.6,3.275 -3.6,3.6 -3.275,3.6 ; 3.275,-3.6 3.6,-3.6 3.6,-3.275 ; 3.275,3.6 3.6,3.6 3.6,3.275
Mechanical 13:
  circle w0.1: c-2.675,2.675 r0.5
  lines w0.1: -3.575,-3.575 3.575,-3.575 3.575,3.575 -3.575,3.575 -3.575,-3.575
Mechanical 15:
  lines w0.1: -0.5,0 0.5,0 ; 0,-0.5 0,0.5 ; -3.9,-3.9 3.9,-3.9 3.9,3.9 -3.9,3.9 -3.9,-3.9
3D body: height 1, standoff 0, extent -3.575,-3.575 3.575,3.575

## QFG48_M [mm] "48-Pin Quad Flat No-Lead (QFG48) - Pb-Free, IPC Low Density"
height 1
pads (49):
  oval 0.9x0.25 smd: 1(-3.55,2.75) 2(-3.55,2.25) 3(-3.55,1.75) 4(-3.55,1.25) 5(-3.55,0.75) 6(-3.55,0.25) 7(-3.55,-0.25) 8(-3.55,-0.75) 9(-3.55,-1.25) 10(-3.55,-1.75) 11(-3.55,-2.25) 12(-3.55,-2.75) 25(3.55,-2.75) 26(3.55,-2.25) 27(3.55,-1.75) 28(3.55,-1.25) 29(3.55,-0.75) 30(3.55,-0.25) 31(3.55,0.25) 32(3.55,0.75) 33(3.55,1.25) 34(3.55,1.75) 35(3.55,2.25) 36(3.55,2.75)
  oval 0.25x0.9 smd: 13(-2.75,-3.55) 14(-2.25,-3.55) 15(-1.75,-3.55) 16(-1.25,-3.55) 17(-0.75,-3.55) 18(-0.25,-3.55) 19(0.25,-3.55) 20(0.75,-3.55) 21(1.25,-3.55) 22(1.75,-3.55) 23(2.25,-3.55) 24(2.75,-3.55) 37(2.75,3.55) 38(2.25,3.55) 39(1.75,3.55) 40(1.25,3.55) 41(0.75,3.55) 42(0.25,3.55) 43(-0.25,3.55) 44(-0.75,3.55) 45(-1.25,3.55) 46(-1.75,3.55) 47(-2.25,3.55) 48(-2.75,3.55)
  rect 5.3x5.3 smd: 49(0,0)
via 1.8,-1.8 diameter 0.66 hole 0.33
via 0.6,-1.8 diameter 0.66 hole 0.33
via -0.6,-1.8 diameter 0.66 hole 0.33
via -1.8,-1.8 diameter 0.66 hole 0.33
via 1.8,-0.6 diameter 0.66 hole 0.33
via 0.6,-0.6 diameter 0.66 hole 0.33
via -0.6,-0.6 diameter 0.66 hole 0.33
via -1.8,-0.6 diameter 0.66 hole 0.33
via 1.8,0.6 diameter 0.66 hole 0.33
via 0.6,0.6 diameter 0.66 hole 0.33
via -0.6,0.6 diameter 0.66 hole 0.33
via -1.8,0.6 diameter 0.66 hole 0.33
via 1.8,1.8 diameter 0.66 hole 0.33
via 0.6,1.8 diameter 0.66 hole 0.33
via -0.6,1.8 diameter 0.66 hole 0.33
via -1.8,1.8 diameter 0.66 hole 0.33
Top Overlay:
  circle w0.25: c-4.55,2.75 r0.125
  lines w0.2: -3.6,-3.275 -3.6,-3.6 -3.275,-3.6 ; -3.6,3.275 -3.6,3.6 -3.275,3.6 ; 3.275,-3.6 3.6,-3.6 3.6,-3.275 ; 3.275,3.6 3.6,3.6 3.6,3.275
Mechanical 13:
  circle w0.1: c-2.675,2.675 r0.5
  lines w0.1: -3.575,-3.575 3.575,-3.575 3.575,3.575 -3.575,3.575 -3.575,-3.575
Mechanical 15:
  lines w0.1: -0.5,0 0.5,0 ; 0,-0.5 0,0.5 ; -4.5,-4.5 4.5,-4.5 4.5,4.5 -4.5,4.5 -4.5,-4.5
3D body: height 1, standoff 0, extent -3.575,-3.575 3.575,3.575

## QFG48_N [mm] "48-Pin Quad Flat No-Lead (QFG48) - Pb-Free, IPC Medium Density"
height 1
pads (49):
  oval 0.8x0.25 smd: 1(-3.5,2.75) 2(-3.5,2.25) 3(-3.5,1.75) 4(-3.5,1.25) 5(-3.5,0.75) 6(-3.5,0.25) 7(-3.5,-0.25) 8(-3.5,-0.75) 9(-3.5,-1.25) 10(-3.5,-1.75) 11(-3.5,-2.25) 12(-3.5,-2.75) 25(3.5,-2.75) 26(3.5,-2.25) 27(3.5,-1.75) 28(3.5,-1.25) 29(3.5,-0.75) 30(3.5,-0.25) 31(3.5,0.25) 32(3.5,0.75) 33(3.5,1.25) 34(3.5,1.75) 35(3.5,2.25) 36(3.5,2.75)
  oval 0.25x0.8 smd: 13(-2.75,-3.5) 14(-2.25,-3.5) 15(-1.75,-3.5) 16(-1.25,-3.5) 17(-0.75,-3.5) 18(-0.25,-3.5) 19(0.25,-3.5) 20(0.75,-3.5) 21(1.25,-3.5) 22(1.75,-3.5) 23(2.25,-3.5) 24(2.75,-3.5) 37(2.75,3.5) 38(2.25,3.5) 39(1.75,3.5) 40(1.25,3.5) 41(0.75,3.5) 42(0.25,3.5) 43(-0.25,3.5) 44(-0.75,3.5) 45(-1.25,3.5) 46(-1.75,3.5) 47(-2.25,3.5) 48(-2.75,3.5)
  rect 5.3x5.3 smd: 49(0,0)
via -1.8,1.8 diameter 0.66 hole 0.33
via -0.6,1.8 diameter 0.66 hole 0.33
via 0.6,1.8 diameter 0.66 hole 0.33
via 1.8,1.8 diameter 0.66 hole 0.33
via -1.8,0.6 diameter 0.66 hole 0.33
via -0.6,0.6 diameter 0.66 hole 0.33
via 0.6,0.6 diameter 0.66 hole 0.33
via 1.8,0.6 diameter 0.66 hole 0.33
via -1.8,-0.6 diameter 0.66 hole 0.33
via -0.6,-0.6 diameter 0.66 hole 0.33
via 0.6,-0.6 diameter 0.66 hole 0.33
via 1.8,-0.6 diameter 0.66 hole 0.33
via -1.8,-1.8 diameter 0.66 hole 0.33
via -0.6,-1.8 diameter 0.66 hole 0.33
via 0.6,-1.8 diameter 0.66 hole 0.33
via 1.8,-1.8 diameter 0.66 hole 0.33
Top Overlay:
  circle w0.25: c-4.45,2.75 r0.125
  lines w0.2: -3.6,-3.275 -3.6,-3.6 -3.275,-3.6 ; -3.6,3.275 -3.6,3.6 -3.275,3.6 ; 3.275,-3.6 3.6,-3.6 3.6,-3.275 ; 3.275,3.6 3.6,3.6 3.6,3.275
Mechanical 13:
  circle w0.1: c-2.675,2.675 r0.5
  lines w0.1: -3.575,-3.575 -3.575,3.575 3.575,3.575 3.575,-3.575 -3.575,-3.575
Mechanical 15:
  lines w0.1: -0.5,0 0.5,0 ; 0,-0.5 0,0.5 ; -4.15,-4.15 -4.15,4.15 4.15,4.15 4.15,-4.15 -4.15,-4.15
3D body: height 1, standoff 0, extent -3.575,-3.575 3.575,3.575

## SF363 [mm] "363-Ball Flip Chip Fine Pitch Ball Grid Array (SF363)"
height 1.99
pads (363):
  round 0.45 smd: A2(-6.8,7.6) A3(-6,7.6) A4(-5.2,7.6) A5(-4.4,7.6) A6(-3.6,7.6) A7(-2.8,7.6) A8(-2,7.6) A9(-1.2,7.6) A10(-0.4,7.6) A11(0.4,7.6) A12(1.2,7.6) A13(2,7.6) A14(2.8,7.6) A15(3.6,7.6) A16(4.4,7.6) A17(5.2,7.6) A18(6,7.6) A19(6.8,7.6) A20(7.6,7.6) B1(-7.6,6.8) B2(-6.8,6.8) B3(-6,6.8) B4(-5.2,6.8) B5(-4.4,6.8) B6(-3.6,6.8) B7(-2.8,6.8) B8(-2,6.8) B9(-1.2,6.8) B10(-0.4,6.8) B11(0.4,6.8) B12(1.2,6.8) B13(2,6.8) B14(2.8,6.8) B15(3.6,6.8) B16(4.4,6.8) B17(5.2,6.8) B18(6,6.8) B19(6.8,6.8) B20(7.6,6.8) C1(-7.6,6) C2(-6.8,6) C3(-6,6) C4(-5.2,6) C5(-4.4,6) C6(-3.6,6) C7(-2.8,6) C8(-2,6) C9(-1.2,6) C10(-0.4,6) C11(0.4,6) C12(1.2,6) C13(2,6) C14(2.8,6) C15(3.6,6) C16(4.4,6) C17(5.2,6) C18(6,6) C19(6.8,6) C20(7.6,6) D1(-7.6,5.2) D2(-6.8,5.2) D3(-6,5.2) D4(-5.2,5.2) D5(-4.4,5.2) D6(-3.6,5.2) D7(-2.8,5.2) D8(-2,5.2) D9(-1.2,5.2) D10(-0.4,5.2) D11(0.4,5.2) D12(1.2,5.2) D13(2,5.2) D14(2.8,5.2) D15(3.6,5.2) D16(4.4,5.2) D17(5.2,5.2) D18(6,5.2) D19(6.8,5.2) D20(7.6,5.2) E1(-7.6,4.4) E2(-6.8,4.4) E3(-6,4.4) E4(-5.2,4.4) E5(-4.4,4.4) E6(-3.6,4.4) E7(-2.8,4.4) E8(-2,4.4) E9(-1.2,4.4) E10(-0.4,4.4) E11(0.4,4.4) E12(1.2,4.4) E13(2,4.4) E14(2.8,4.4) E15(3.6,4.4) E16(4.4,4.4) E17(5.2,4.4) E18(6,4.4) E19(6.8,4.4) E20(7.6,4.4) F1(-7.6,3.6) F2(-6.8,3.6) F3(-6,3.6) F4(-5.2,3.6) F5(-4.4,3.6) F6(-3.6,3.6) F7(-2.8,3.6) F8(-2,3.6) F9(-1.2,3.6) F10(-0.4,3.6) F11(0.4,3.6) F12(1.2,3.6) F13(2,3.6) F14(2.8,3.6) F15(3.6,3.6) F16(4.4,3.6) F17(5.2,3.6) F18(6,3.6) F19(6.8,3.6) F20(7.6,3.6) G1(-7.6,2.8) G2(-6.8,2.8) G3(-6,2.8) G4(-5.2,2.8) G5(-4.4,2.8) G6(-3.6,2.8) G7(-2.8,2.8) G8(-2,2.8) G9(-1.2,2.8) G10(-0.4,2.8) G11(0.4,2.8) G12(1.2,2.8) G13(2,2.8) G14(2.8,2.8) G15(3.6,2.8) G16(4.4,2.8) G17(5.2,2.8) G18(6,2.8) G19(6.8,2.8) G20(7.6,2.8) H1(-7.6,2) H2(-6.8,2) H3(-6,2) H4(-5.2,2) H5(-4.4,2) H6(-3.6,2) H7(-2.8,2) H14(2.8,2) H15(3.6,2) H16(4.4,2) H17(5.2,2) H18(6,2) H19(6.8,2) H20(7.6,2) J1(-7.6,1.2) J2(-6.8,1.2) J3(-6,1.2) J4(-5.2,1.2) J5(-4.4,1.2) J6(-3.6,1.2) J7(-2.8,1.2) J14(2.8,1.2) J15(3.6,1.2) J16(4.4,1.2) J17(5.2,1.2) J18(6,1.2) J19(6.8,1.2) J20(7.6,1.2) K1(-7.6,0.4) K2(-6.8,0.4) K3(-6,0.4) K4(-5.2,0.4) K5(-4.4,0.4) K6(-3.6,0.4) K7(-2.8,0.4) K14(2.8,0.4) K15(3.6,0.4) K16(4.4,0.4) K17(5.2,0.4) K18(6,0.4) K19(6.8,0.4) K20(7.6,0.4) L1(-7.6,-0.4) L2(-6.8,-0.4) L3(-6,-0.4) L4(-5.2,-0.4) L5(-4.4,-0.4) L6(-3.6,-0.4) L7(-2.8,-0.4) L14(2.8,-0.4) L15(3.6,-0.4) L16(4.4,-0.4) L17(5.2,-0.4) L18(6,-0.4) L19(6.8,-0.4) L20(7.6,-0.4) M1(-7.6,-1.2) M2(-6.8,-1.2) M3(-6,-1.2) M4(-5.2,-1.2) M5(-4.4,-1.2) M6(-3.6,-1.2) M7(-2.8,-1.2) M14(2.8,-1.2) M15(3.6,-1.2) M16(4.4,-1.2) M17(5.2,-1.2) M18(6,-1.2) M19(6.8,-1.2) M20(7.6,-1.2) N1(-7.6,-2) N2(-6.8,-2) N3(-6,-2) N4(-5.2,-2) N5(-4.4,-2) N6(-3.6,-2) N7(-2.8,-2) N14(2.8,-2) N15(3.6,-2) N16(4.4,-2) N17(5.2,-2) N18(6,-2) N19(6.8,-2) N20(7.6,-2) P1(-7.6,-2.8) P2(-6.8,-2.8) P3(-6,-2.8) P4(-5.2,-2.8) P5(-4.4,-2.8) P6(-3.6,-2.8) P7(-2.8,-2.8) P8(-2,-2.8) P9(-1.2,-2.8) P10(-0.4,-2.8) P11(0.4,-2.8) P12(1.2,-2.8) P13(2,-2.8) P14(2.8,-2.8) P15(3.6,-2.8) P16(4.4,-2.8) P17(5.2,-2.8) P18(6,-2.8) P19(6.8,-2.8) P20(7.6,-2.8) R1(-7.6,-3.6) R2(-6.8,-3.6) R3(-6,-3.6) R4(-5.2,-3.6) R5(-4.4,-3.6) R6(-3.6,-3.6) R7(-2.8,-3.6) R8(-2,-3.6) R9(-1.2,-3.6) R10(-0.4,-3.6) R11(0.4,-3.6) R12(1.2,-3.6) R13(2,-3.6) R14(2.8,-3.6) R15(3.6,-3.6) R16(4.4,-3.6) R17(5.2,-3.6) R18(6,-3.6) R19(6.8,-3.6) R20(7.6,-3.6) T1(-7.6,-4.4) T2(-6.8,-4.4) T3(-6,-4.4) T4(-5.2,-4.4) T5(-4.4,-4.4) T6(-3.6,-4.4) T7(-2.8,-4.4) T8(-2,-4.4) T9(-1.2,-4.4) T10(-0.4,-4.4) T11(0.4,-4.4) T12(1.2,-4.4) T13(2,-4.4) T14(2.8,-4.4) T15(3.6,-4.4) T16(4.4,-4.4) T17(5.2,-4.4) T18(6,-4.4) T19(6.8,-4.4) T20(7.6,-4.4) U1(-7.6,-5.2) U2(-6.8,-5.2) U3(-6,-5.2) U4(-5.2,-5.2) U5(-4.4,-5.2) U6(-3.6,-5.2) U7(-2.8,-5.2) U8(-2,-5.2) U9(-1.2,-5.2) U10(-0.4,-5.2) U11(0.4,-5.2) U12(1.2,-5.2) U13(2,-5.2) U14(2.8,-5.2) U15(3.6,-5.2) U16(4.4,-5.2) U17(5.2,-5.2) U18(6,-5.2) U19(6.8,-5.2) U20(7.6,-5.2) V1(-7.6,-6) V2(-6.8,-6) V3(-6,-6) V4(-5.2,-6) V5(-4.4,-6) V6(-3.6,-6) V7(-2.8,-6) V8(-2,-6) V9(-1.2,-6) V10(-0.4,-6) V11(0.4,-6) V12(1.2,-6) V13(2,-6) V14(2.8,-6) V15(3.6,-6) V16(4.4,-6) V17(5.2,-6) V18(6,-6) V19(6.8,-6) V20(7.6,-6) W1(-7.6,-6.8) W2(-6.8,-6.8) W3(-6,-6.8) W4(-5.2,-6.8) W5(-4.4,-6.8) W6(-3.6,-6.8) W7(-2.8,-6.8) W8(-2,-6.8) W9(-1.2,-6.8) W10(-0.4,-6.8) W11(0.4,-6.8) W12(1.2,-6.8) W13(2,-6.8) W14(2.8,-6.8) W15(3.6,-6.8) W16(4.4,-6.8) W17(5.2,-6.8) W18(6,-6.8) W19(6.8,-6.8) W20(7.6,-6.8) Y1(-7.6,-7.6) Y2(-6.8,-7.6) Y3(-6,-7.6) Y4(-5.2,-7.6) Y5(-4.4,-7.6) Y6(-3.6,-7.6) Y7(-2.8,-7.6) Y8(-2,-7.6) Y9(-1.2,-7.6) Y10(-0.4,-7.6) Y11(0.4,-7.6) Y12(1.2,-7.6) Y13(2,-7.6) Y14(2.8,-7.6) Y15(3.6,-7.6) Y16(4.4,-7.6) Y17(5.2,-7.6) Y18(6,-7.6) Y19(6.8,-7.6) Y20(7.6,-7.6)
Top Overlay:
  circle w0.25: c-9.15,7.6 r0.125
  region: -7.584,8.5 -8.5,7.584 -8.5,8.5
  lines w0.2: -8.5,7.584 -7.584,8.5 ; -8.5,-8.5 8.5,-8.5 8.5,8.5 -8.5,8.5 -8.5,-8.5
Mechanical 13:
  lines w0.1: -8.5,-8.5 8.5,-8.5 8.5,8.5 -8.5,8.5 -8.5,-8.5
Mechanical 15:
  lines w0.1: -0.5,0 0.5,0 ; 0,-0.5 0,0.5 ; -9.5,-9.5 9.5,-9.5 9.5,9.5 -9.5,9.5 -9.5,-9.5
3D body: height 1.99, standoff 0, extent -8.5,-8.5 8.5,8.5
